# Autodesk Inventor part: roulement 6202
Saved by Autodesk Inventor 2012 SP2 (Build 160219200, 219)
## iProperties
Created: 2013-04
Part Number: roulement 6202
Material: Default
Document SubType Name: Modeling
Designer: papa
Density: 1 g/cm^3
Mass: 5.59723 g
Surface Area: 53.0923 cm^2
Volume: 5.59723 cm^3
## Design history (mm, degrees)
node "roulement 62021"
node "roulement 6202"
node "roulement 6202_1"
node "roulement 6202_2"
node "roulement 6202_3"
node "roulement 6202_4"
node "roulement 6202_5"
node "roulement 6202_6"
node "roulement 6202_7"
node "roulement 6202_8"
node "roulement 6202_9"
node "Base1"
node "Base2"
node "Base3"
node "Base4"
node "Base5"
node "Base6"
node "Base7"
node "Base8"
node "Base9"
node "Base10"
